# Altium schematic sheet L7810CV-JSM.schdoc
size 127 x 101 mm
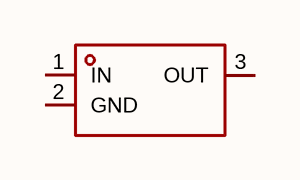
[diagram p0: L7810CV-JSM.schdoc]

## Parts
U?  l7810cv-jsm  [TO-220-3_L10.0-W4.6-P2.54-L]  (value not drawn)

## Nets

Not connected (* = marked no-connect by the designer): U? 1(IN) 2(GND) 3(OUT)

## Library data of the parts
U? = l7810cv-jsm: 输出极性:正极;工作电压:35V;输出电压:10V;输出电流:1.5A;电源纹波抑制比(PSRR):56dB@(120Hz);输出类型:固定;; Manufacturer: JSMSEMI(杰盛微); AddInBom: yes; ModelId: 711528d35a164a8f8c6ce62cc2c792eb; ModelTransform: 401.574,178.58232,0,0,0,0,0,26.575,-196.85; Output Configuration: 正极; Voltage - Supply: 35V; Output Voltage: 10V; Output Current: 1.5A; Voltage Dropout: 2V; standby current: 8mA; Noise: 58uV; Output Type: 固定; Number of Outputs: 1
